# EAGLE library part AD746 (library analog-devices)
Dual Precision, 500 ns Settling, BiFET Op Amp Source: http://www.analog.com/static/imported-files/data_sheets/AD746.pdf
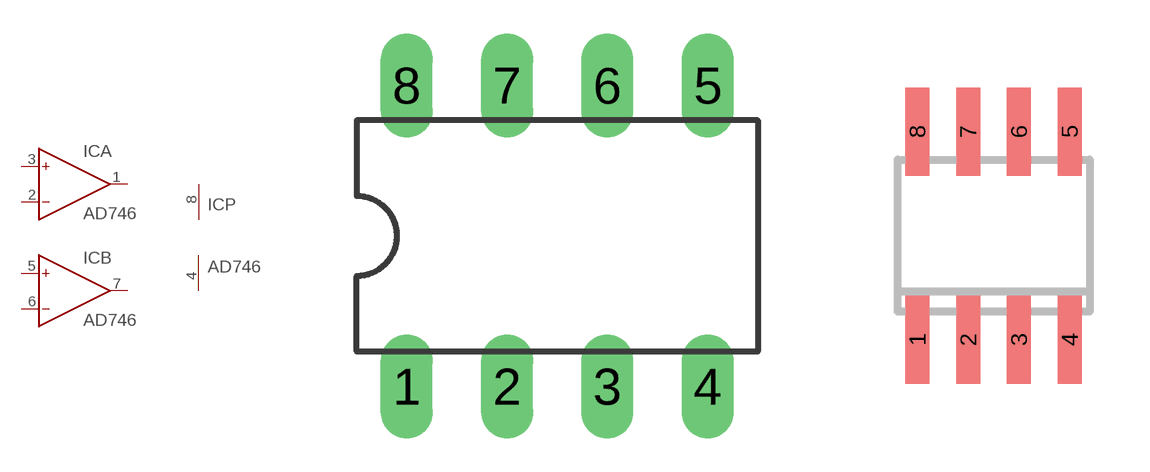
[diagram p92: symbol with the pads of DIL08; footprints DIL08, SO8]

Designator prefix IC; gates A=OP B=OP P=PWR+-

## AD746N (MF: ALTERA CORPORATION; MPN: AD746JNZ; OC_FARNELL: 1438363; OC_NEWARK: 59K4844)  [DIL08]
1  A:OUT  out
2  A:IN-  in
3  A:IN+  in
4  P:V-  pwr
5  B:IN+  in
6  B:IN-  in
7  B:OUT  out
8  P:V+  pwr

## AD746R (MF: ALTERA CORPORATION; MPN: AD746JRZ; OC_FARNELL: 1423876; OC_NEWARK: 59K4845)  [SO8]

## Footprint DIL08 (pad centres in mm)
Dual In Line Package
drill 0.813 long: 1 -3.81,-3.81; 2 -1.27,-3.81; 3 1.27,-3.81; 4 3.81,-3.81; 5 3.81,3.81; 6 1.27,3.81; 7 -1.27,3.81; 8 -3.81,3.81

## Footprint SO8 (pad centres in mm)
8-Lead Small Outline IC (SO-8) Source: http://www.analog.com/UploadedFiles/Data_Sheets/703465986AD8611_2_0.pdf
smd 0.6 x 2.2: 1 -1.905,-2.6; 2 -0.635,-2.6; 3 0.635,-2.6; 4 1.905,-2.6; 5 1.905,2.6; 6 0.635,2.6; 7 -0.635,2.6; 8 -1.905,2.6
